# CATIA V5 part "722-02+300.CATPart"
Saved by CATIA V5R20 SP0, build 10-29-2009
Part number: 722-02+300
Revision: TUTTO
Definition: NON CONOSCIUTO
Nomenclature: 722-02+300
Source: Unknown
Bounding box of the stored display mesh (mm): x -45.5 to 20, y -20 to 45.333, z -5 to 300
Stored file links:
  C:\Users\Utente\Desktop\IO LAVORO\3D X SITO CF\ULTIMI CATALOGO VERDE\3D files 722\722-02+300.CATPart
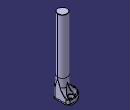
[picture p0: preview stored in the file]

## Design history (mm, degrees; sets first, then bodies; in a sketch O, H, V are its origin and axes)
Body1 "Smusso4" (main body)
  Solid1: solid without history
